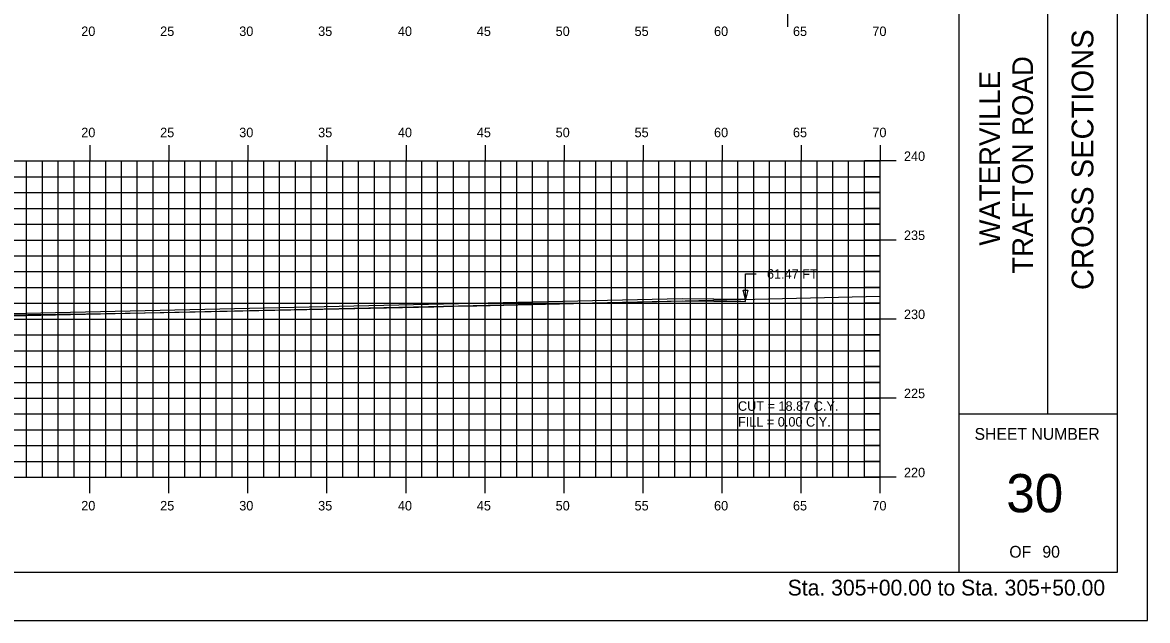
# Model space of a CAD drawing. Extents: x 1137211 to 1137381, y 608981 to 609091.
# Drawn here: x 1137309.6 to 1137380.8, y 608981.3 to 609019.1 of the extents above; entities that cross this region are included whole.
import ezdxf

# ---------------------------------------------------------------- set-up
doc = ezdxf.new("R2010")
doc.units = 0
for name, color, linetype in [('BORDER', 7, 'Continuous'), ('D_Drainage_Ditch_Line', 7, 'Continuous'), ('D_Roadway_Edge_Shoulder', 7, 'Continuous'), ('D_Text_Standard', 7, 'Continuous'), ('H_V ANNOTATION', 7, 'Continuous'), ('HIGHWAY_TITLE', 7, 'Continuous'), ('MAJOR', 7, 'Continuous'), ('MINOR', 7, 'Continuous'), ('PLOT BOUNDARY', 7, 'Continuous'), ('S_Roadway_Centerline', 7, 'Continuous')]:
    doc.layers.add(name, color=color, linetype=linetype)

msp = doc.modelspace()

# ---------------------------------------------------------------- linework, layer by layer
at = {"layer": 'BORDER'}
for p, q in [((1137368.897, 608984.335), (1137368.897, 609089.335)), ((1137374.488, 608994.338), (1137374.488, 609029.338)), ((1137368.897, 608994.338), (1137378.897, 608994.338))]:
    msp.add_line(p, q, dxfattribs=at)
msp.add_lwpolyline([(1137218.897, 608984.335), (1137378.897, 608984.335), (1137378.897, 609089.335), (1137218.897, 609089.335)], close=True, dxfattribs=at)
at = {"layer": 'D_Drainage_Ditch_Line'}
msp.add_line((1137358.036, 609025.06), (1137358.036, 609018.817), dxfattribs=at)
at = {"layer": 'D_Roadway_Edge_Shoulder'}
msp.add_lwpolyline([(1137355.366, 609001.58), (1137351.367, 609001.609), (1137308.896, 609000.659), (1137308.896, 609000.534), (1137351.367, 609001.484), (1137355.365, 609001.455)], close=True, dxfattribs=at)
at = {"layer": 'D_Text_Standard'}
msp.add_lwpolyline([(1137355.366, 609001.58), (1137355.371, 609003.19), (1137356.051, 609003.19)], dxfattribs=at)
msp.add_lwpolyline([(1137355.366, 609001.58), (1137355.223, 609002.163), (1137355.514, 609002.162)], close=True, dxfattribs=at)
at = {"layer": 'MAJOR'}
for p, q in [((1137313.896, 609011.337), (1137313.896, 609010.335)), ((1137318.896, 609011.337), (1137318.896, 609010.335)), ((1137323.896, 609011.337), (1137323.896, 609010.335)), ((1137328.896, 609011.337), (1137328.896, 609010.335)), ((1137333.896, 609011.337), (1137333.896, 609010.335)), ((1137338.896, 609011.337), (1137338.896, 609010.335)), ((1137343.896, 609011.337), (1137343.896, 609010.335)), ((1137348.896, 609011.337), (1137348.896, 609010.335)), ((1137353.896, 609011.337), (1137353.896, 609010.335)), ((1137358.896, 609011.337), (1137358.896, 609010.335)), ((1137363.896, 609011.337), (1137363.896, 609010.335)), ((1137223.896, 609010.335), (1137363.896, 609010.335)), ((1137223.896, 609010.335), (1137363.896, 609010.335)), ((1137313.896, 608990.335), (1137313.896, 609010.335)), ((1137318.896, 608990.335), (1137318.896, 609010.335)), ((1137323.896, 608990.335), (1137323.896, 609010.335)), ((1137328.896, 608990.335), (1137328.896, 609010.335)), ((1137333.896, 608990.335), (1137333.896, 609010.335)), ((1137338.896, 608990.335), (1137338.896, 609010.335)), ((1137343.896, 608990.335), (1137343.896, 609010.335)), ((1137348.896, 608990.335), (1137348.896, 609010.335)), ((1137353.896, 608990.335), (1137353.896, 609010.335)), ((1137358.896, 608990.335), (1137358.896, 609010.335)), ((1137364.898, 609010.335), (1137362.894, 609010.335)), ((1137363.896, 608990.335), (1137363.896, 609010.335)), ((1137363.896, 608990.335), (1137363.896, 609010.335)), ((1137223.896, 609005.335), (1137363.896, 609005.335)), ((1137364.898, 609005.335), (1137362.894, 609005.335)), ((1137223.896, 609000.335), (1137363.896, 609000.335)), ((1137364.898, 609000.335), (1137362.894, 609000.335)), ((1137223.896, 608995.335), (1137363.896, 608995.335)), ((1137364.898, 608995.335), (1137362.894, 608995.335)), ((1137223.896, 608990.335), (1137363.896, 608990.335)), ((1137223.896, 608990.335), (1137363.896, 608990.335)), ((1137313.896, 608989.333), (1137313.896, 608990.335)), ((1137318.896, 608989.333), (1137318.896, 608990.335)), ((1137323.896, 608989.333), (1137323.896, 608990.335)), ((1137328.896, 608989.333), (1137328.896, 608990.335)), ((1137333.896, 608989.333), (1137333.896, 608990.335)), ((1137338.896, 608989.333), (1137338.896, 608990.335)), ((1137343.896, 608989.333), (1137343.896, 608990.335)), ((1137348.896, 608989.333), (1137348.896, 608990.335)), ((1137353.896, 608989.333), (1137353.896, 608990.335)), ((1137358.896, 608989.333), (1137358.896, 608990.335)), ((1137364.898, 608990.335), (1137362.894, 608990.335)), ((1137363.896, 608989.333), (1137363.896, 608990.335))]:
    msp.add_line(p, q, dxfattribs=at)
at = {"layer": 'MINOR'}
for p, q in [((1137309.896, 608990.335), (1137309.896, 609010.335)), ((1137310.896, 608990.335), (1137310.896, 609010.335)), ((1137311.896, 608990.335), (1137311.896, 609010.335)), ((1137312.896, 608990.335), (1137312.896, 609010.335)), ((1137314.896, 608990.335), (1137314.896, 609010.335)), ((1137315.896, 608990.335), (1137315.896, 609010.335)), ((1137316.896, 608990.335), (1137316.896, 609010.335)), ((1137317.896, 608990.335), (1137317.896, 609010.335)), ((1137319.896, 608990.335), (1137319.896, 609010.335)), ((1137320.896, 608990.335), (1137320.896, 609010.335)), ((1137321.896, 608990.335), (1137321.896, 609010.335)), ((1137322.896, 608990.335), (1137322.896, 609010.335)), ((1137324.896, 608990.335), (1137324.896, 609010.335)), ((1137325.896, 608990.335), (1137325.896, 609010.335)), ((1137326.896, 608990.335), (1137326.896, 609010.335)), ((1137327.896, 608990.335), (1137327.896, 609010.335)), ((1137329.896, 608990.335), (1137329.896, 609010.335)), ((1137330.896, 608990.335), (1137330.896, 609010.335)), ((1137331.896, 608990.335), (1137331.896, 609010.335)), ((1137332.896, 608990.335), (1137332.896, 609010.335)), ((1137334.896, 608990.335), (1137334.896, 609010.335)), ((1137335.896, 608990.335), (1137335.896, 609010.335)), ((1137336.896, 608990.335), (1137336.896, 609010.335)), ((1137337.896, 608990.335), (1137337.896, 609010.335)), ((1137339.896, 608990.335), (1137339.896, 609010.335)), ((1137340.896, 608990.335), (1137340.896, 609010.335)), ((1137341.896, 608990.335), (1137341.896, 609010.335)), ((1137342.896, 608990.335), (1137342.896, 609010.335)), ((1137344.896, 608990.335), (1137344.896, 609010.335)), ((1137345.896, 608990.335), (1137345.896, 609010.335)), ((1137346.896, 608990.335), (1137346.896, 609010.335)), ((1137347.896, 608990.335), (1137347.896, 609010.335)), ((1137349.896, 608990.335), (1137349.896, 609010.335)), ((1137350.896, 608990.335), (1137350.896, 609010.335)), ((1137351.896, 608990.335), (1137351.896, 609010.335)), ((1137352.896, 608990.335), (1137352.896, 609010.335)), ((1137354.896, 608990.335), (1137354.896, 609010.335)), ((1137355.896, 608990.335), (1137355.896, 609010.335)), ((1137356.896, 608990.335), (1137356.896, 609010.335)), ((1137357.896, 608990.335), (1137357.896, 609010.335)), ((1137359.896, 608990.335), (1137359.896, 609010.335)), ((1137360.896, 608990.335), (1137360.896, 609010.335)), ((1137361.896, 608990.335), (1137361.896, 609010.335)), ((1137362.896, 608990.335), (1137362.896, 609010.335)), ((1137223.896, 609009.335), (1137363.896, 609009.335)), ((1137363.896, 609009.335), (1137362.894, 609009.335)), ((1137223.896, 609008.335), (1137363.896, 609008.335)), ((1137363.896, 609008.335), (1137362.894, 609008.335)), ((1137223.896, 609007.335), (1137363.896, 609007.335)), ((1137363.896, 609007.335), (1137362.894, 609007.335)), ((1137223.896, 609006.335), (1137363.896, 609006.335)), ((1137363.896, 609006.335), (1137362.894, 609006.335)), ((1137223.896, 609004.335), (1137363.896, 609004.335)), ((1137363.896, 609004.335), (1137362.894, 609004.335)), ((1137223.896, 609003.335), (1137363.896, 609003.335)), ((1137363.896, 609003.335), (1137362.894, 609003.335)), ((1137223.896, 609002.335), (1137363.896, 609002.335)), ((1137363.896, 609002.335), (1137362.894, 609002.335)), ((1137223.896, 609001.335), (1137363.896, 609001.335)), ((1137363.896, 609001.335), (1137362.894, 609001.335)), ((1137223.896, 608999.335), (1137363.896, 608999.335)), ((1137363.896, 608999.335), (1137362.894, 608999.335)), ((1137223.896, 608998.335), (1137363.896, 608998.335)), ((1137363.896, 608998.335), (1137362.894, 608998.335)), ((1137223.896, 608997.335), (1137363.896, 608997.335)), ((1137363.896, 608997.335), (1137362.894, 608997.335)), ((1137223.896, 608996.335), (1137363.896, 608996.335)), ((1137363.896, 608996.335), (1137362.894, 608996.335)), ((1137223.896, 608994.335), (1137363.896, 608994.335)), ((1137363.896, 608994.335), (1137362.894, 608994.335)), ((1137223.896, 608993.335), (1137363.896, 608993.335)), ((1137363.896, 608993.335), (1137362.894, 608993.335)), ((1137223.896, 608992.335), (1137363.896, 608992.335)), ((1137363.896, 608992.335), (1137362.894, 608992.335)), ((1137223.896, 608991.335), (1137363.896, 608991.335)), ((1137363.896, 608991.335), (1137362.894, 608991.335))]:
    msp.add_line(p, q, dxfattribs=at)
at = {"layer": 'PLOT BOUNDARY'}
msp.add_lwpolyline([(1137210.803, 608981.276), (1137380.803, 608981.276), (1137380.803, 609091.276), (1137210.803, 609091.276)], close=True, dxfattribs=at)
at = {"layer": 'S_Roadway_Centerline'}
msp.add_lwpolyline([(1137306.22, 609000.583), (1137313.681, 609000.675), (1137318.576, 609000.754), (1137319.535, 609000.78), (1137334.677, 609001.08), (1137335.653, 609001.109), (1137336.885, 609001.145), (1137338.373, 609001.176), (1137340.079, 609001.211), (1137363.896, 609001.786)], dxfattribs=at)

# ---------------------------------------------------------------- texts
at = {"layer": 'BORDER'}
msp.add_text('CROSS SECTIONS', height=1.37787, rotation=90, dxfattribs=at).set_placement((1137377.381, 609002.172))
for s, height, p in [('SHEET NUMBER', 0.74527, (1137369.862, 608992.701)), ('30', 2.4194, (1137371.872, 608988.118)), ('OF', 0.7453, (1137372.063, 608985.248)), ('90', 0.7453, (1137374.153, 608985.248))]:
    msp.add_text(s, height=height, dxfattribs=at).set_placement(p)
at = {"layer": 'D_Text_Standard'}
for s, p in [('61.47 FT', (1137356.731, 609002.89)), ('CUT = 18.87 C.Y.', (1137354.896, 608994.535)), ('FILL = 0.00 C.Y.', (1137354.896, 608993.539))]:
    msp.add_text(s, height=0.6, dxfattribs=at).set_placement(p)
at = {"layer": 'H_V ANNOTATION'}
for s, height, p in [('20', 0.6, (1137313.35, 609018.235)), ('25', 0.6, (1137318.342, 609018.235)), ('30', 0.6, (1137323.345, 609018.235)), ('35', 0.6, (1137328.337, 609018.235)), ('40', 0.6, (1137333.382, 609018.235)), ('45', 0.6, (1137338.374, 609018.235)), ('50', 0.6, (1137343.361, 609018.235)), ('55', 0.6, (1137348.353, 609018.235)), ('60', 0.6, (1137353.382, 609018.235)), ('65', 0.6, (1137358.374, 609018.235)), ('70', 0.6, (1137363.398, 609018.235)), ('20', 0.6, (1137313.35, 609011.835)), ('25', 0.6, (1137318.342, 609011.835)), ('30', 0.6, (1137323.345, 609011.835)), ('35', 0.6, (1137328.337, 609011.835)), ('40', 0.6, (1137333.382, 609011.835)), ('45', 0.6, (1137338.374, 609011.835)), ('50', 0.6, (1137343.361, 609011.835)), ('55', 0.6, (1137348.353, 609011.835)), ('60', 0.6, (1137353.382, 609011.835)), ('65', 0.6, (1137358.374, 609011.835)), ('70', 0.6, (1137363.398, 609011.835)), ('240', 0.6, (1137365.396, 609010.335)), ('235', 0.6, (1137365.396, 609005.335)), ('230', 0.6, (1137365.396, 609000.335)), ('225', 0.6, (1137365.396, 608995.335)), ('220', 0.6, (1137365.396, 608990.335)), ('20', 0.6, (1137313.35, 608988.235)), ('25', 0.6, (1137318.342, 608988.235)), ('30', 0.6, (1137323.345, 608988.235)), ('35', 0.6, (1137328.337, 608988.235)), ('40', 0.6, (1137333.382, 608988.235)), ('45', 0.6, (1137338.374, 608988.235)), ('50', 0.6, (1137343.361, 608988.235)), ('55', 0.6, (1137348.353, 608988.235)), ('60', 0.6, (1137353.382, 608988.235)), ('65', 0.6, (1137358.374, 608988.235)), ('70', 0.6, (1137363.398, 608988.235)), ('Sta. 305+00.00 to Sta. 305+50.00', 1.0002, (1137358.042, 608982.855))]:
    msp.add_text(s, height=height, dxfattribs=at).set_placement(p)
at = {"layer": 'HIGHWAY_TITLE'}
for s, height, p in [('TRAFTON ROAD', 1.30428, (1137373.556, 609003.201)), ('WATERVILLE', 1.3043, (1137371.469, 609004.98))]:
    msp.add_text(s, height=height, rotation=90, dxfattribs=at).set_placement(p)

doc.saveas('drawing.dxf')
